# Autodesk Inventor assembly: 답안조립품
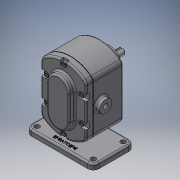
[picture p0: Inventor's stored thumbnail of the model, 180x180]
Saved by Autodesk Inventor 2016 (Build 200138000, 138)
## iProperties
Created: 2019-03
Part Number: 답안조립품
Document SubType Name: Assembly
Designer: MIRAE
Author: MIRAE
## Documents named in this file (11)
- C:\Users\MIRAE\Desktop\490307V1011\답안조립품.iam
- C:\Users\MIRAE\Desktop\490307V1011\본체.ipt
- C:\Users\MIRAE\Desktop\490307V1011\개스킷.ipt
- C:\Users\MIRAE\Desktop\490307V1011\커버.ipt
- C:\Users\MIRAE\Desktop\490307V1011\볼트 M5.ipt
- C:\Users\MIRAE\Desktop\490307V1011\서브축.ipt
- C:\Users\MIRAE\Desktop\490307V1011\메인축.ipt
- C:\Users\MIRAE\Desktop\490307V1011\베어링부시.ipt
- C:\Users\MIRAE\Desktop\490307V1011\키 6 x 6 x 18.ipt
- C:\Users\MIRAE\Desktop\490307V1011\스퍼기어.ipt
- C:\Users\MIRAE\Desktop\490307V1011\오일 실 16 28 7.ipt
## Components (1 placed, 1 different names)
1. 개스킷:1
